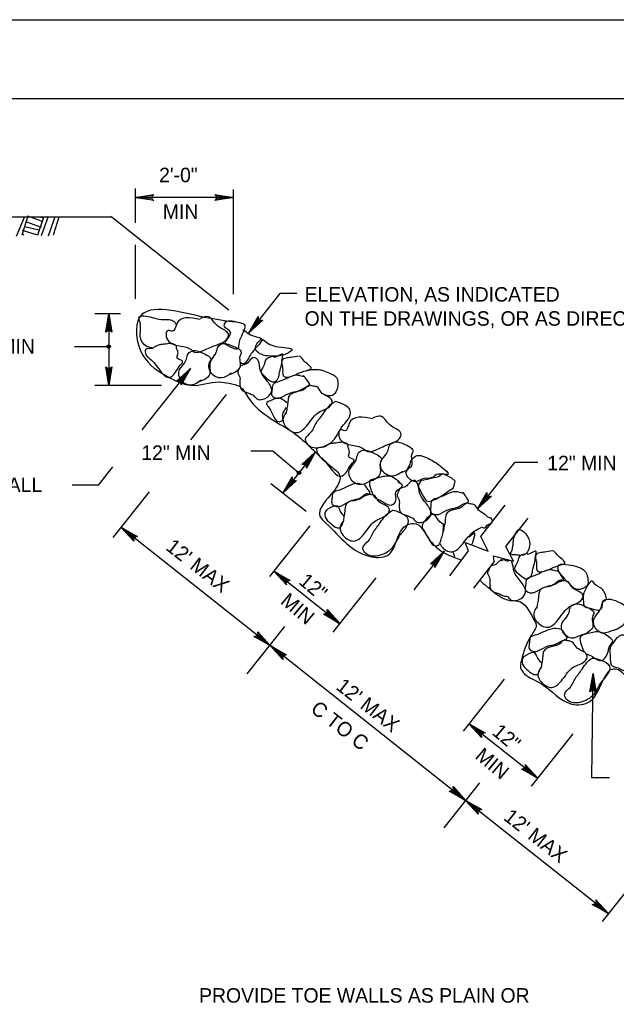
# Model space of a CAD drawing. Extents: x 5 to 910, y -47 to 547.
# Drawn here: x 606.1 to 719.1, y 360.5 to 547.5 of the extents above; entities that cross this region are included whole.
import ezdxf

# ---------------------------------------------------------------- set-up
doc = ezdxf.new("R2010")
doc.units = 0
for name, color, linetype in [('1', 7, 'Continuous'), ('2', 7, 'Continuous'), ('3', 7, 'Continuous'), ('PLT-BNDY', 7, 'Continuous')]:
    doc.layers.add(name, color=color, linetype=linetype)

msp = doc.modelspace()

# ---------------------------------------------------------------- linework, layer by layer
at = {"layer": '1'}
for p, q in [((623.41, 510.09), (600.07, 510.09)), ((606.89, 510.02), (605.36, 506.39)), ((607.62, 510.23), (606.43, 506.68)), ((610.16, 508.13), (607.41, 509.13)), ((610.37, 509.25), (607.57, 510.23)), ((610.53, 510.02), (609.41, 506.66)), ((610.57, 509.91), (610.05, 510.02)), ((611.44, 510.18), (610.11, 506.55)), ((612.63, 509.91), (611.42, 506.46)), ((613.48, 510.07), (612.4, 506.62)), ((606.82, 506.68), (606.57, 506.91)), ((609.41, 506.66), (606.61, 507.51)), ((609.73, 507.58), (606.98, 508.22))]:
    msp.add_line(p, q, dxfattribs=at)
msp.add_lwpolyline([(830.72, -31.53), (830.72, 532.47), (44.72, 532.47), (44.72, -31.53), (830.72, -31.53), (830.72, -5.17), (630.72, -5.17), (630.72, 59.51), (830.72, 59.51), (830.72, 88.47), (630.72, 88.47), (630.72, -31.53), (709.52, -31.53), (709.52, -5.17), (709.52, -31.53), (786.52, -31.53), (786.52, -5.17), (786.52, -17.48), (830.72, -17.48)], dxfattribs=at)
at = {"layer": '2'}
for p, q in [((627.94, 515.52), (627.94, 508.97)), ((646.51, 515.31), (646.51, 495.45)), ((646.51, 513.78), (627.94, 513.78)), ((645.71, 492.45), (623.34, 510.16)), ((627.94, 504.79), (627.94, 494.58)), ((655.37, 495.61), (649.49, 488.15)), ((658.55, 495.61), (655.37, 495.61)), ((625.15, 491.74), (620.27, 491.74)), ((622.93, 491.74), (622.93, 478.18)), ((622.93, 485.52), (616.45, 485.52)), ((622.93, 485.52), (616.45, 485.52)), ((638.39, 481.38), (629.22, 469.78)), ((632.92, 478.18), (620.27, 478.18)), ((645.21, 476.48), (638.42, 467.88)), ((654.06, 465.75), (649.88, 465.75)), ((654.06, 465.75), (658.89, 461.68)), ((662.14, 465.62), (655.92, 457.75)), ((623.64, 462.73), (620.89, 459.26)), ((699.8, 463.6), (692.84, 454.8)), ((704.26, 463.6), (699.8, 463.6)), ((620.89, 459.26), (616.02, 459.26)), ((660.31, 454.27), (653.65, 459.55)), ((630.59, 458), (623.72, 449.33)), ((653.53, 428.87), (625.3, 451.27)), ((661.03, 451.59), (653.4, 441.94)), ((686.48, 446.74), (680.72, 439.44)), ((666.69, 433.08), (654.22, 442.96)), ((673.52, 441.72), (665.38, 431.43)), ((656.23, 432.5), (649.11, 423.51)), ((690.55, 399.54), (653.53, 428.87)), ((697.84, 422.5), (690.07, 412.67)), ((714.49, 403.82), (714.72, 423.59)), ((704.23, 403.75), (691.19, 414.07)), ((710.88, 412.17), (703, 402.22)), ((717.83, 403.82), (714.49, 403.82)), ((693.18, 402.88), (686.42, 394.34)), ((717.64, 378.08), (690.55, 399.54)), ((734.57, 399.52), (716.43, 376.57))]:
    msp.add_line(p, q, dxfattribs=at)
for points in [[(631.25, 513.36), (631.14, 513.59), (627.94, 513.78), (631.25, 513.36), (631.44, 513.2), (627.94, 513.78), (631.14, 513.94), (631.25, 514.17), (627.94, 513.78), (631.44, 514.33), (631.25, 514.17)], [(643.2, 514.19), (643.31, 513.96), (646.51, 513.78), (643.2, 514.19), (643.01, 514.35), (646.51, 513.78), (643.31, 513.62), (643.2, 513.39), (646.51, 513.78), (643.01, 513.23), (643.2, 513.39)], [(622.51, 488.43), (622.74, 488.54), (622.93, 491.74), (622.51, 488.43), (622.35, 488.24), (622.93, 491.74), (623.09, 488.54), (623.32, 488.43), (622.93, 491.74), (623.48, 488.24), (623.32, 488.43)], [(651.87, 490.51), (651.62, 490.55), (649.49, 488.15), (651.87, 490.51), (652.1, 490.55), (649.49, 488.15), (651.34, 490.76), (651.23, 490.99), (649.49, 488.15), (651.23, 491.24), (651.23, 490.99)], [(623.34, 481.49), (623.11, 481.38), (622.93, 478.18), (623.34, 481.49), (623.5, 481.68), (622.93, 478.18), (622.77, 481.38), (622.54, 481.49), (622.93, 478.18), (622.38, 481.68), (622.54, 481.49)], [(636.01, 479.02), (636.26, 478.98), (638.39, 481.38), (636.01, 479.02), (635.78, 478.98), (638.39, 481.38), (636.54, 478.77), (636.65, 478.54), (638.39, 481.38), (636.65, 478.29), (636.65, 478.54)], [(659.76, 463.26), (660.01, 463.21), (662.14, 465.62), (659.76, 463.26), (659.53, 463.21), (662.14, 465.62), (660.29, 463.01), (660.4, 462.78), (662.14, 465.62), (660.4, 462.53), (660.4, 462.78)], [(658.3, 460.1), (658.05, 460.15), (655.92, 457.75), (658.3, 460.1), (658.53, 460.15), (655.92, 457.75), (657.77, 460.35), (657.66, 460.58), (655.92, 457.75), (657.66, 460.84), (657.66, 460.58)], [(686.16, 461.41), (685.41, 460.88), (684.9, 460.7), (684.4, 460.68), (683.19, 460.35), (682.09, 460.08), (681.61, 459.42), (681.61, 458.89), (682.53, 457.2), (683.1, 456.31), (683.78, 456.19), (684.93, 456.65), (686.3, 457.47), (687.47, 458.25), (688.18, 458.71), (688.36, 459.21), (688.59, 460.03), (687.92, 460.63), (687.08, 461.02), (686.28, 461.41)], [(695.22, 457.15), (694.97, 457.2), (692.84, 454.8), (695.22, 457.15), (695.45, 457.2), (692.84, 454.8), (694.7, 457.4), (694.58, 457.63), (692.84, 454.8), (694.58, 457.88), (694.58, 457.63)], [(627.66, 448.87), (627.7, 449.14), (625.3, 451.27), (627.66, 448.87), (627.68, 448.66), (625.3, 451.27), (627.91, 449.42), (628.14, 449.53), (625.3, 451.27), (628.39, 449.53), (628.14, 449.53)], [(684.1, 444.39), (684.36, 444.34), (686.48, 446.74), (684.1, 444.39), (683.88, 444.34), (686.48, 446.74), (684.63, 444.13), (684.74, 443.91), (686.48, 446.74), (684.74, 443.65), (684.74, 443.91)], [(656.58, 440.56), (656.62, 440.84), (654.22, 442.96), (656.58, 440.56), (656.6, 440.36), (654.22, 442.96), (656.83, 441.11), (657.06, 441.23), (654.22, 442.96), (657.31, 441.23), (657.06, 441.23)], [(664.33, 435.48), (664.29, 435.21), (666.69, 433.08), (664.33, 435.48), (664.31, 435.69), (666.69, 433.08), (664.08, 434.93), (663.85, 434.82), (666.69, 433.08), (663.6, 434.82), (663.85, 434.82)], [(651.2, 431.27), (651.13, 431), (653.53, 428.87), (651.2, 431.27), (651.15, 431.48), (653.53, 428.87), (650.92, 430.72), (650.7, 430.61), (653.53, 428.87), (650.44, 430.61), (650.7, 430.61)], [(655.89, 426.47), (655.94, 426.74), (653.53, 428.87), (655.89, 426.47), (655.91, 426.26), (653.53, 428.87), (656.14, 427.02), (656.37, 427.13), (653.53, 428.87), (656.62, 427.13), (656.37, 427.13)], [(693.55, 411.69), (693.59, 411.94), (691.19, 414.07), (693.55, 411.69), (693.59, 411.46), (691.19, 414.07), (693.8, 412.22), (694.03, 412.33), (691.19, 414.07), (694.28, 412.33), (694.03, 412.33)], [(701.88, 406.13), (701.83, 405.88), (704.23, 403.75), (701.88, 406.13), (701.83, 406.36), (704.23, 403.75), (701.62, 405.6), (701.4, 405.49), (704.23, 403.75), (701.14, 405.49), (701.4, 405.49)], [(688.19, 401.94), (688.15, 401.67), (690.55, 399.54), (688.19, 401.94), (688.17, 402.15), (690.55, 399.54), (687.94, 401.39), (687.71, 401.28), (690.55, 399.54), (687.46, 401.28), (687.71, 401.28)], [(715.28, 380.48), (715.24, 380.21), (717.64, 378.08), (715.28, 380.48), (715.26, 380.69), (717.64, 378.08), (715.03, 379.93), (714.8, 379.82), (717.64, 378.08), (714.55, 379.82), (714.8, 379.82)]]:
    msp.add_lwpolyline(points, dxfattribs=at)
for centre in [(622.91, 485.54), (658.99, 461.63)]:
    msp.add_circle(centre, 0.326, dxfattribs=at)
at = {"layer": '3'}
for p, q in [((659.17, 480.08), (659.99, 479.87)), ((689.34, 457.98), (690.17, 457.77)), ((693.44, 449.53), (698.06, 455.46)), ((698.2, 447.68), (702.41, 453.03)), ((687.54, 442.1), (691.13, 446.86)), ((688.11, 446.67), (688.47, 445.74)), ((698.29, 445.14), (698.24, 445.12)), ((696, 444.84), (692.04, 439.79)), ((707.26, 443.2), (708.08, 442.99))]:
    msp.add_line(p, q, dxfattribs=at)
for points in [[(645.69, 487.4), (645.12, 486.64), (645, 486.44), (644.91, 486.05)], [(691.13, 446.86), (690.46, 448.39), (694.81, 446.74), (693.44, 449.53)], [(696, 444.84), (695.82, 445.9), (699.62, 444.89), (698.2, 447.68)], [(714.26, 420.27), (714.51, 420.39), (714.72, 423.59), (714.26, 420.27), (714.12, 420.11), (714.72, 423.59), (714.83, 420.39), (715.08, 420.27), (714.72, 423.59), (715.24, 420.09), (715.08, 420.27)], [(692.91, 397.14), (692.95, 397.41), (690.55, 399.54), (692.91, 397.14), (692.93, 396.93), (690.55, 399.54), (693.16, 397.69), (693.39, 397.8), (690.55, 399.54), (693.64, 397.8), (693.39, 397.8)]]:
    msp.add_lwpolyline(points, dxfattribs=at)
for points in [[(647.02, 490.14), (641.02, 491.08), (628.78, 491.08), (629.29, 484.08), (634.53, 479.62), (638.48, 478.2), (643.84, 478.84), (645.74, 478.59), (647.77, 477.95), (649.42, 475.78), (658.37, 468.89), (665.25, 462.67), (666.76, 460.86), (666.53, 459.74), (665.5, 458.07), (662.96, 453.35), (664.09, 452.05), (672.76, 445.71), (676.1, 446.19), (677.08, 447.73), (679.39, 451.68), (681.18, 451.96), (682.82, 450.29), (685.02, 447.47), (689.78, 445.09)], [(631.32, 485.25), (630.5, 485.41), (629.06, 486.73), (628.85, 490.17), (628.65, 490.97), (631.14, 491.08), (632.9, 490.67), (634.87, 490.55), (635.6, 489.94), (635.69, 489.73)], [(640.22, 490.69), (635.78, 489.8), (634.98, 488.43), (634.16, 488.59), (633.82, 487.44), (636.01, 485.75), (638.46, 485.02), (639.24, 484.45), (640.79, 484.79), (643.47, 485.89), (644.98, 486.64), (645.64, 487.69), (643.47, 489.55), (641.78, 491.2), (640.22, 490.85)], [(645.69, 487.37), (646.03, 488.29), (644.87, 489.32), (644.96, 490.05), (647.36, 490.17), (648.6, 489.73), (647.89, 487.15), (647.54, 485.59), (647.54, 485.41), (644.96, 486)], [(648.32, 488.79), (650.91, 487.37), (651.87, 487.05), (650.7, 485.18), (649.26, 483.12), (648.32, 482.27), (648.02, 482.5)], [(635.67, 485.75), (634.85, 486.09), (633.77, 486.02), (632.86, 485.91), (632.22, 485.75), (631.67, 485.48), (631.14, 485.2), (629.88, 484.95), (630.04, 483.94), (630.96, 483.03), (634.75, 479.78), (635.58, 480.69), (636.49, 482.02), (636.93, 482.75), (635.92, 483.37), (636.04, 484.13), (636.04, 484.58), (635.74, 485.48), (635.85, 485.75)], [(646.08, 480.56), (645.69, 480.19), (643.72, 479.64), (642.03, 481.08), (641.96, 482.3), (642.44, 483.12), (643.31, 484.49), (643.68, 485.52), (644.62, 486.12), (646.47, 485.61), (647.84, 484.84), (648, 484.49), (647.77, 483.67), (647.84, 482.39), (647.61, 481.33), (647.54, 481.24), (646.4, 480.44), (645.74, 480.21)], [(652.1, 486.89), (654.61, 485.57), (657.66, 484.9), (655.8, 483.9), (653.95, 483.74), (652.26, 483.9), (650.75, 485.06), (651.91, 487.08)], [(640.38, 479.21), (639.99, 478.84), (638.03, 478.27), (636.33, 479.76), (636.24, 480.97), (636.75, 481.77), (637.64, 483.14), (637.96, 484.19), (638.92, 484.77), (640.79, 484.26), (642.14, 483.46), (642.3, 483.14), (642.1, 482.34), (642.14, 481.06), (641.89, 479.98), (641.85, 479.92), (640.7, 479.09), (640.04, 478.86)], [(654.18, 483.69), (652.6, 482.89), (652.42, 482.2), (651.78, 480.83), (652.78, 479.62), (654.27, 478.86), (655.03, 479.53), (655.3, 480.72), (655.67, 482.11), (655.85, 483.51), (655.92, 484.06), (654.27, 483.51), (654.18, 483.51)], [(650.5, 476.16), (651.23, 475.52), (651.71, 475.48), (652.58, 475.71), (653.79, 477.01), (653.01, 478.93), (651.64, 481.08), (651.25, 482.87), (650.79, 483.37), (650.5, 483.46), (649.53, 482.75), (648.83, 482.18), (647.86, 481.75), (647.61, 481.2), (647.38, 480.74), (647.77, 479.73), (647.8, 479.23), (647.84, 477.97), (648.12, 477.33), (648.64, 477.01), (649.49, 476.71), (649.85, 476.53), (650.56, 476.21)], [(658.87, 483.74), (657.47, 483.46), (656.54, 483.37), (656.05, 483.19), (655.71, 482.73), (655.8, 481.98), (655.89, 481.15), (656.15, 479.85), (656.72, 479.76), (658.3, 480.21), (659.88, 480.85), (661.27, 481.4), (659.78, 483), (659.51, 483.37), (659.05, 483.74)], [(660.49, 481.04), (662.96, 481.15), (663.7, 480.95), (664.93, 480.42), (665.78, 480.01), (666.37, 478.36), (666.08, 477.22), (665.34, 476.28), (663.9, 476.39)], [(659.23, 480.03), (658.57, 480.1), (656.9, 479.64), (655.23, 478.93), (654.06, 478.36), (653.84, 477.22), (653.84, 476.28), (654.98, 475.75), (655.62, 475.91), (657.43, 476.8), (658.71, 477.08), (660.36, 477.9), (661, 478.27), (660.65, 478.96), (660.17, 479.66), (659.83, 480.03)], [(656.49, 472.96), (655.96, 471.86), (656.01, 471.25), (656.58, 470.26), (658.55, 469.23), (660.63, 470.76), (662.8, 473.14), (664.84, 474.2), (665.27, 474.88), (665.27, 475.29), (664.13, 476.21), (663.19, 476.87), (662.39, 477.9), (661.59, 478.06), (660.97, 478.18), (659.9, 477.38), (659.3, 477.17), (657.82, 476.71), (657.11, 476.19), (656.9, 475.43), (656.79, 474.29), (656.7, 473.81), (656.54, 472.87)], [(656.65, 474.91), (655.21, 475.75), (653.86, 475.41), (652.83, 474.7), (653.15, 474.17), (653.97, 472.73), (655.21, 471.29), (655.83, 471.61), (655.94, 472.62), (656.54, 473.97)], [(665.92, 475.13), (666.99, 474.75), (668.71, 473.37), (668.34, 471.86), (667.11, 470.31), (665.73, 468.02), (663.06, 466.46), (660.72, 466.9), (660.17, 467.9), (661.29, 469.37), (662.39, 471.34), (662.83, 471.86), (663.51, 472.82), (664.36, 473.94), (665.37, 474.81), (665.92, 475.13)], [(672.96, 471.84), (668.52, 470.99), (667.7, 469.58), (666.88, 469.76), (666.53, 468.61), (668.73, 466.92), (671.18, 466.19), (671.98, 465.64), (673.51, 465.94), (676.19, 467.08), (677.72, 467.79), (678.36, 468.87), (676.19, 470.72), (674.49, 472.34), (672.96, 472.02)], [(668.16, 467.04), (667.36, 467.4), (666.28, 467.29), (665.37, 467.2), (664.7, 467.04), (664.18, 466.76), (663.65, 466.49), (662.39, 466.21), (662.55, 465.21), (663.44, 464.31), (667.24, 461.04), (668.09, 461.96), (668.98, 463.31), (669.42, 464.04), (668.43, 464.66), (668.52, 465.39), (668.52, 465.85), (668.25, 466.76), (668.34, 467.04)], [(678.61, 461.93), (678.22, 461.59), (676.28, 461.02), (674.56, 462.46), (674.49, 463.7), (674.98, 464.52), (675.87, 465.89), (676.21, 466.92), (677.17, 467.49), (679.02, 467.01), (680.37, 466.21), (680.56, 465.89), (680.33, 465.07), (680.37, 463.76), (680.17, 462.73), (680.08, 462.64), (678.93, 461.84), (678.27, 461.61)], [(672.64, 460.31), (672.25, 459.99), (670.31, 459.39), (668.59, 460.86), (668.52, 462.07), (669, 462.87), (669.9, 464.29), (670.22, 465.32), (671.18, 465.89), (673.05, 465.39), (674.43, 464.59), (674.59, 464.29), (674.36, 463.47), (674.43, 462.16), (674.17, 461.11), (674.11, 461.02), (672.96, 460.19), (672.3, 459.99)], [(680.12, 463.67), (681.06, 464.79), (683.85, 464.15), (686.12, 462.62), (687.26, 461.38), (685.06, 461.27), (684.17, 460.65), (682.71, 460.56), (681.06, 459.94), (679.3, 461.68), (679.92, 462.92), (680.12, 463.76)], [(678.18, 459.69), (676.33, 460.93), (673.83, 460.63), (672.37, 459.9), (672.57, 458.55), (673.72, 456.69), (674.04, 456.58), (676.6, 455.55), (677.35, 456.37), (677.35, 456.97), (677.35, 457.93), (678.59, 459.26), (677.77, 459.81)], [(680.67, 452.92), (681.4, 452.28), (681.91, 452.21), (682.78, 452.42), (683.97, 453.74), (683.21, 455.66), (681.82, 457.82), (681.43, 459.6), (680.97, 460.13), (680.67, 460.19), (679.73, 459.51), (679, 458.91), (678.06, 458.5), (677.79, 457.93), (677.56, 457.5), (677.95, 456.49), (678, 455.99), (678.02, 454.73), (678.29, 454.06), (678.82, 453.74), (679.69, 453.45), (680.05, 453.26), (680.76, 452.97)], [(684.63, 460.88), (683.97, 460.65), (683.88, 460.65)], [(670.63, 459.49), (669.99, 459.58), (668.32, 459.1), (666.65, 458.36), (665.46, 457.82), (665.23, 456.69), (665.23, 455.76), (666.35, 455.21), (667.01, 455.39), (668.82, 456.28), (670.08, 456.53), (671.77, 457.38), (672.41, 457.72), (672.05, 458.43), (671.59, 459.12), (671.25, 459.51)], [(689.34, 457.98), (688.7, 458.04), (687.03, 457.59), (685.36, 456.88), (684.17, 456.31), (683.94, 455.16), (683.94, 454.22), (685.06, 453.7), (685.73, 453.86), (687.54, 454.75), (688.79, 455.02), (690.49, 455.87), (691.13, 456.21), (690.76, 456.9), (690.3, 457.61), (689.96, 457.98)], [(667.29, 452.42), (666.76, 451.32), (666.83, 450.72), (667.38, 449.72), (669.37, 448.69), (671.45, 450.22), (673.58, 452.6), (675.62, 453.65), (676.1, 454.36), (676.1, 454.77), (674.95, 455.66), (673.99, 456.35), (673.17, 457.36), (672.41, 457.52), (671.8, 457.63), (670.7, 456.85), (670.13, 456.65), (668.62, 456.19), (667.93, 455.66), (667.72, 454.89), (667.59, 453.77), (667.49, 453.29), (667.36, 452.35)], [(667.56, 453.4), (666.81, 454.41), (666.3, 455.3), (664.75, 454.91), (663.99, 454.27), (664.11, 452.87), (664.75, 452.23), (665.92, 451.32), (666.67, 451.2), (667.33, 452.37)], [(676.83, 454.57), (677.93, 454.18), (679.64, 452.8), (679.3, 451.32), (678.06, 449.74), (676.65, 447.43), (673.99, 445.9), (671.68, 446.33), (671.11, 447.31), (672.21, 448.82), (673.33, 450.77), (673.76, 451.32), (674.43, 452.26), (675.3, 453.4), (676.28, 454.25), (676.85, 454.59)], [(694.79, 453.22), (693.96, 453.88), (693.03, 454.57), (692.23, 455.57), (691.45, 455.73), (690.83, 455.85), (689.73, 455.05), (689.16, 454.84), (687.65, 454.41), (686.94, 453.86), (686.73, 453.1), (686.62, 451.96), (686.51, 451.5), (686.37, 450.54)], [(686.69, 451.73), (685.41, 452.62), (684.49, 453.7), (682.82, 452.55), (682.32, 451.62), (683.03, 450.06), (685.09, 447.79), (685.64, 448.18), (685.93, 449.03), (686.25, 450.06), (686.35, 451.32), (686.35, 451.82)], [(693.62, 451.32), (694.22, 451.2), (694.83, 451.84), (695.13, 451.96), (695.45, 452.05), (695.63, 452.53), (695.52, 452.85), (694.72, 453.22)], [(685.75, 448.14), (685.98, 447.68), (687.97, 446.65), (690.03, 448.18), (692.2, 450.54), (693.62, 451.32)], [(699.62, 448.92), (700.74, 450.86), (701.97, 450.04), (702.7, 448.05), (701.67, 446.08), (700.74, 445.99), (699.96, 446.1)], [(691.75, 447.91), (692.09, 449.03), (692.29, 450.17), (691.26, 449.44)], [(699.59, 448.98), (699.52, 448.44), (699.46, 447.73), (699.39, 447.34), (699.34, 446.93), (699.09, 446.38), (699.23, 446.22), (699.94, 446.17)], [(702.2, 446.35), (700.62, 445.55), (700.44, 444.87), (699.8, 443.49), (700.81, 442.28), (702.29, 441.53), (703.02, 442.19), (703.32, 443.38), (703.69, 444.77), (703.85, 446.17), (703.96, 446.72), (702.29, 446.17), (702.2, 446.17)], [(706.94, 446.83), (705.56, 446.58), (704.65, 446.47), (704.15, 446.31), (703.8, 445.85), (703.89, 445.09), (703.99, 444.25), (704.24, 442.94), (704.83, 442.88), (706.39, 443.31), (707.97, 443.97), (709.36, 444.52), (707.87, 446.12), (707.6, 446.47), (707.12, 446.83)], [(697.4, 445.16), (696.87, 444.8), (696.14, 444.2), (695.2, 443.79), (694.93, 443.22), (694.7, 442.78), (695.09, 441.75), (695.13, 441.27), (695.18, 440.02), (695.43, 439.35), (695.95, 439.03), (696.85, 438.73), (697.19, 438.55), (697.9, 438.25)], [(697.26, 445.07), (697.28, 445.03), (697.74, 445.19), (698.17, 445.03), (698.65, 444.96), (698.93, 445.07), (699.27, 444.91)], [(698.59, 438.09), (699.32, 437.45), (699.82, 437.38), (700.69, 437.59), (701.88, 438.92), (701.15, 440.84), (699.73, 442.99), (699.34, 444.77), (699.3, 444.87)], [(707.33, 443.13), (706.69, 443.22), (705.01, 442.76), (703.34, 442.03), (702.16, 441.46), (701.93, 440.34), (701.93, 439.4), (703.05, 438.87), (703.71, 439.03), (705.52, 439.92), (706.78, 440.2), (708.47, 441.02), (709.11, 441.39), (708.74, 442.07), (708.29, 442.76), (707.94, 443.15)], [(708.49, 444.32), (710.57, 444.11), (713.34, 442.76), (713.75, 441.3), (713.66, 440.38), (713.25, 439.97), (711.28, 439.63), (710.57, 440.27), (709.52, 441.3), (709.2, 441.71), (708.17, 443.08), (708.08, 443.79), (708.38, 444.32)], [(693.23, 441.25), (696, 438.96), (698.93, 437.45), (700.46, 437.32), (703.39, 434.02), (703.92, 432.74), (703, 430.82), (701.13, 426.08), (700.97, 424.69), (701.74, 423.54), (704.92, 421.64), (710.67, 417.8), (714.12, 418.3), (716.29, 421.64), (717.19, 423.29), (718.33, 424.44), (719.47, 424.32), (721.53, 422.15), (726.86, 418.05), (731.83, 414.99), (734.51, 411.81), (737.57, 409.02), (738.83, 408.49), (739.72, 407.99), (740, 407.55)], [(703.99, 436.08), (703.46, 434.98), (703.53, 434.36), (704.08, 433.38), (706.07, 432.35), (708.15, 433.86), (710.28, 436.26), (712.31, 437.32), (712.79, 438), (712.79, 438.41), (711.65, 439.33), (710.69, 439.99), (709.87, 441.02), (709.11, 441.18), (708.49, 441.27), (707.39, 440.5), (706.82, 440.29), (705.31, 439.83), (704.63, 439.31), (704.42, 438.55), (704.28, 437.41), (704.19, 436.93), (704.03, 435.99)], [(717.3, 437.73), (716.36, 439.63), (714.83, 440.77), (714.62, 441.07), (713.78, 440.43), (713.46, 439.88), (712.98, 438.89), (712.84, 438.12), (712.91, 437), (713, 436.45), (714.14, 435.94), (715.7, 435.62), (716.34, 435.9), (716.57, 437.29), (717.25, 437.71)], [(697.9, 438.25), (698.63, 438.09), (698.65, 438.05)], [(718.76, 431.78), (718.6, 431.76), (716.66, 431.21), (714.94, 432.65), (714.88, 433.86), (715.36, 434.69), (716.25, 436.08), (716.59, 437.11), (717.55, 437.68), (719.41, 437.2), (720.78, 436.4), (720.94, 436.08), (720.71, 435.26), (720.78, 433.95), (720.55, 432.92), (720.46, 432.81), (719.31, 432.01), (718.65, 431.78)], [(712.65, 430.92), (712.5, 430.86), (710.57, 430.29), (708.86, 431.76), (708.77, 432.97), (709.27, 433.77), (710.16, 435.17), (710.46, 436.2), (711.44, 436.77), (713.3, 436.29), (714.67, 435.46), (714.85, 435.17), (714.6, 434.34), (714.67, 433.04), (714.44, 431.99), (714.35, 431.92), (713.23, 431.09), (712.54, 430.89)], [(708.77, 431.94), (707.37, 432.1), (705.7, 431.64), (704.03, 430.93), (702.84, 430.38), (702.61, 429.22), (702.61, 428.3), (703.76, 427.75), (704.4, 427.94), (706.23, 428.81), (707.46, 429.1), (709.16, 429.93), (709.8, 430.27), (709.43, 430.98), (708.97, 431.67), (708.63, 432.05)], [(718.06, 430.25), (716.02, 431.42), (713.73, 431.16), (712.27, 430.45), (712.47, 429.08), (713.62, 427.23), (713.91, 427.14), (716.52, 426.11), (717.23, 426.93), (717.6, 427.76), (717.74, 428.59), (718.47, 429.81), (718.02, 430.28)], [(720.62, 424.05), (721.35, 423.41), (721.85, 423.31), (722.72, 423.54), (723.94, 424.87), (723.18, 426.81), (721.76, 428.94), (721.21, 430.54), (720.96, 430.71), (719.75, 430.71), (719.68, 430.64), (718.95, 430.04), (718.46, 429.27), (718.05, 428.72), (717.9, 428.06), (717.9, 427.59), (717.94, 427.11), (717.99, 425.85), (718.24, 425.17), (718.76, 424.87), (719.66, 424.57), (720, 424.39), (720.71, 424.07)], [(704.81, 424.66), (704.28, 423.57), (704.33, 422.95), (704.88, 421.99), (706.89, 420.94), (708.95, 422.49), (711.1, 424.85), (713.14, 425.9), (713.59, 426.61), (713.59, 427.02), (712.45, 427.94), (711.51, 428.62), (710.69, 429.61), (709.91, 429.79), (709.29, 429.9), (708.2, 429.08), (707.62, 428.87), (706.14, 428.46), (705.43, 427.91), (705.22, 427.16), (705.08, 426.01), (705.01, 425.53), (704.85, 424.6)], [(704.95, 425.58), (704.19, 426.59), (703.67, 427.48), (702.13, 427.09), (701.35, 426.45), (701.51, 425.05), (702.13, 424.41), (703.28, 423.5), (704.05, 423.38), (704.69, 424.55)], [(714.74, 426.52), (716.22, 426.11), (717.83, 424.98), (717.48, 423.5), (716.25, 421.94), (714.85, 419.63), (712.2, 418.1), (709.87, 418.53), (709.32, 419.52), (710.41, 421.03), (711.54, 422.95), (711.97, 423.5), (712.63, 424.44), (713.5, 425.58), (714.49, 426.45), (714.76, 426.52)]]:
    msp.add_spline(points, degree=3, dxfattribs=at)
at = {"layer": 'PLT-BNDY'}
msp.add_lwpolyline([(4.72, 547.47), (845.72, 547.47), (845.72, -46.53), (4.72, -46.53)], close=True, dxfattribs=at)

# ---------------------------------------------------------------- texts
at = {"layer": '2'}
msp.add_text('PROVIDE TOE WALLS AS PLAIN OR', height=2.7454, dxfattribs=at).set_placement((640.05, 361.22))
at = {"layer": '3'}
for s, height, p in [('2\'-0"', 2.745, (632.47, 516.69)), (' MIN', 2.745, (632.16, 509.73)), ('ELEVATION, AS INDICATED', 2.7454, (660.05, 494.06)), ('ON THE DRAWINGS, OR AS DIRECTED.', 2.7454, (660.05, 489.49)), ('12" MIN', 2.745, (595.8, 484.21)), ('12" MIN', 2.745, (629.1, 464.06)), ('12" MIN', 2.745, (706.04, 462.11)), ('CUT-OFF WALL', 2.7454, (583.19, 457.98))]:
    msp.add_text(s, height=height, dxfattribs=at).set_placement(p)
for s, rotation, p in [("12' MAX ", 322, (633.55, 447.18)), ('12"', 320, (658.75, 440.73)), ('MIN', 320, (655.28, 436.98)), ("12' MAX ", 322, (665.81, 420.76)), (' C TO C', 322, (660.19, 417.11)), ('12"', 320, (695.39, 412.18)), ('MIN', 320, (692.17, 407.65)), ("12' MAX ", 322, (697.57, 396.01))]:
    msp.add_text(s, height=2.745, rotation=rotation, dxfattribs=at).set_placement(p)

doc.saveas('drawing.dxf')
